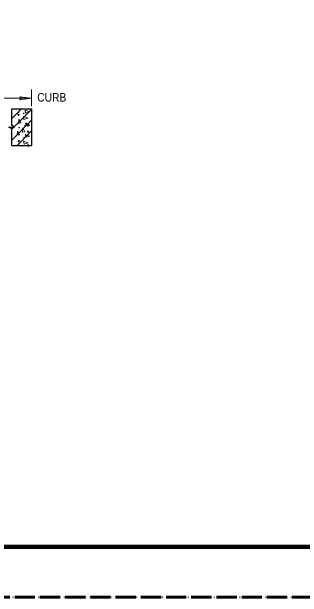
# Model space of a CAD drawing. Extents: x 312583 to 312854, y 144419 to 144597.
# Drawn here: x 312669.7 to 312695.6, y 144418.6 to 144470.8 of the extents above; entities that cross this region are included whole.
import ezdxf

# ---------------------------------------------------------------- set-up
doc = ezdxf.new("R2010")
doc.units = 0
doc.header["$LTSCALE"] = 0.3
doc.header["$PDMODE"] = 32
doc.header["$PDSIZE"] = 0.15
doc.linetypes.add('DOTTED', pattern=[1.5, 0.3, -1.2])
doc.linetypes.add('LONG_DASHED', pattern=[7.5, 6, -1.5])
for name, color, linetype, lineweight in [('1', 7, 'Continuous', 13), ('62', 7, 'DOTTED', 13), ('63', 7, 'LONG_DASHED', 60)]:
    doc.layers.add(name, color=color, linetype=linetype, lineweight=lineweight)

msp = doc.modelspace()

# ---------------------------------------------------------------- linework, layer by layer
at = {"layer": '1'}
for p, q in [((312671.4549, 144463.8819), (312671.4549, 144462.4099)), ((312660.4992, 144463.1153), (312671.4549, 144463.1153)), ((312669.6839, 144461.3059), (312670.5579, 144462.1799)), ((312669.6839, 144460.3476), (312671.4549, 144462.1186)), ((312669.6839, 144459.3893), (312671.4549, 144461.1603)), ((312670.1592, 144458.9063), (312671.4549, 144460.2019))]:
    msp.add_line(p, q, dxfattribs=at)
at = {"layer": '1', "lineweight": 25}
for p, q in [((312669.6839, 144462.1799), (312671.4549, 144462.1799)), ((312671.4549, 144462.1799), (312671.4549, 144458.9063)), ((312669.6839, 144458.9063), (312671.4549, 144458.9063))]:
    msp.add_line(p, q, dxfattribs=at)
at = {"layer": '1', "lineweight": 158}
msp.add_line((312616.5, 144423.0846), (312849, 144423.0846), dxfattribs=at)
at = {"layer": '1'}
for points in [[(312670.4199, 144463.2456), (312671.4549, 144463.1153), (312670.4199, 144462.9773), (312670.5196, 144463.1153)], [(312670.8722, 144462.0419), (312670.9259, 144461.7889), (312671.2939, 144461.8963)], [(312670.7189, 144461.4746), (312670.7726, 144461.2139), (312671.1406, 144461.3289)], [(312671.2709, 144460.7233), (312670.9029, 144460.9226), (312671.1252, 144460.6389)], [(312670.1822, 144459.8109), (312670.2129, 144460.1789), (312670.3816, 144459.8416)], [(312670.8799, 144459.8876), (312670.9336, 144459.6346), (312671.3016, 144459.7419)], [(312670.7342, 144459.2743), (312670.7956, 144459.0136), (312671.1636, 144459.1286)]]:
    msp.add_lwpolyline(points, close=True, dxfattribs=at)
at = {"layer": '1', "lineweight": 25}
msp.add_lwpolyline([(312669.6839, 144458.9063), (312669.6839, 144460.3783), (312669.4309, 144460.5393), (312669.9369, 144460.5393), (312669.6839, 144460.7079), (312669.6839, 144462.1799)], dxfattribs=at)
at = {"layer": '1'}
for points in [[(312670.2819, 144460.8843), (312670.3126, 144461.2523), (312670.4812, 144460.9073), (312670.2819, 144460.8766)], [(312670.6422, 144460.0946), (312670.6729, 144460.4626), (312670.8416, 144460.1253), (312670.6499, 144460.0946)]]:
    msp.add_lwpolyline(points, dxfattribs=at)
for centre, radius in [((312670.2761, 144461.8483), 0.0288), ((312670.2915, 144461.6212), 0.0565), ((312670.7572, 144461.7669), 0.0288), ((312670.3519, 144460.4904), 0.0288), ((312670.8991, 144460.661), 0.0565), ((312671.1329, 144460.1358), 0.0565), ((312670.3106, 144459.28), 0.0565), ((312670.7764, 144459.5666), 0.0288)]:
    msp.add_circle(centre, radius, dxfattribs=at)
msp.add_point((312671.1559, 144458.8909), dxfattribs=at)
at = {"layer": '62'}
msp.add_lwpolyline([(312601.2, 144418.5846), (312853.5, 144418.5846), (312853.5, 144596.7846)], dxfattribs=at)
at = {"layer": '63'}
msp.add_line((312851.75, 144418.5846), (312583.526, 144418.5846), dxfattribs=at)

# ---------------------------------------------------------------- texts
at = {"layer": '1', "width": 0.9}
msp.add_text('CURB', height=0.76, dxfattribs=at).set_placement((312671.9585, 144462.8139))

doc.saveas('drawing.dxf')
